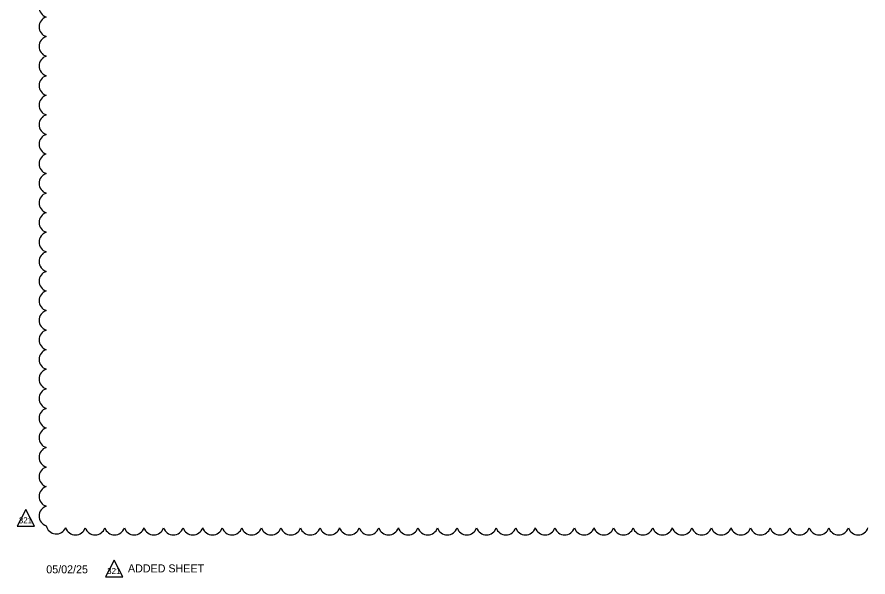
# Model space of a CAD drawing. Extents: x -811 to -795.3, y -2245.7 to -2235.4.
# Drawn here: x -811.04 to -803.6, y -2245.53 to -2240.63 of the extents above; entities that cross this region are included whole.
import ezdxf

# ---------------------------------------------------------------- set-up
doc = ezdxf.new("R2010")
doc.units = 0
doc.layers.add('ScratchEle_dp', color=7, linetype='Continuous')
doc.layers.add('TextITSLabel', color=7, linetype='Continuous')

msp = doc.modelspace()

# ---------------------------------------------------------------- linework, layer by layer
at = {"layer": 'ScratchEle_dp'}
for centre, radius, start, end in [((-810.7597, -2240.5475), 0.0897, 107.5, 252.5), ((-810.7597, -2240.7186), 0.0897, 107.5, 252.5), ((-810.7597, -2240.8897), 0.0897, 107.5, 252.5), ((-810.7597, -2241.0609), 0.0897, 107.5, 252.5), ((-810.7597, -2241.232), 0.0897, 107.5, 252.5), ((-810.7597, -2241.4031), 0.0897, 107.5, 252.5), ((-810.7597, -2241.5742), 0.0897, 107.5, 252.5), ((-810.7597, -2241.7453), 0.0897, 107.5, 252.5), ((-810.7597, -2241.9165), 0.0897, 107.5, 252.5), ((-810.7597, -2242.0876), 0.0897, 107.5, 252.5), ((-810.7597, -2242.2587), 0.0897, 107.5, 252.5), ((-810.7597, -2242.4298), 0.0897, 107.5, 252.5), ((-810.7597, -2242.601), 0.0897, 107.5, 252.5), ((-810.7597, -2242.7721), 0.0897, 107.5, 252.5), ((-810.7597, -2242.9432), 0.0897, 107.5, 252.5), ((-810.7597, -2243.1143), 0.0897, 107.5, 252.5), ((-810.7597, -2243.2854), 0.0897, 107.5, 252.5), ((-810.7597, -2243.4566), 0.0897, 107.5, 252.5), ((-810.7597, -2243.6277), 0.0897, 107.5, 252.5), ((-810.7597, -2243.7988), 0.0897, 107.5, 252.5), ((-810.7597, -2243.9699), 0.0897, 107.5, 252.5), ((-810.7597, -2244.1411), 0.0897, 107.5, 252.5), ((-810.7597, -2244.3122), 0.0897, 107.5, 252.5), ((-810.7597, -2244.4833), 0.0897, 107.5, 252.5), ((-810.7597, -2244.6544), 0.0897, 107.5, 252.5), ((-810.7597, -2244.8255), 0.0897, 107.5, 252.5), ((-810.7597, -2244.9967), 0.0897, 107.5, 252.5), ((-810.699, -2245.064), 0.0896, 191.74536, 336.74536), ((-810.531, -2245.0724), 0.0897, 197.5, 342.5), ((-810.3599, -2245.0724), 0.0897, 197.5, 342.5), ((-810.1888, -2245.0724), 0.0897, 197.5, 342.5), ((-810.0177, -2245.0724), 0.0897, 197.5, 342.5), ((-809.8466, -2245.0724), 0.0897, 197.5, 342.5), ((-809.6754, -2245.0724), 0.0897, 197.5, 342.5), ((-809.5043, -2245.0724), 0.0897, 197.5, 342.5), ((-809.3332, -2245.0724), 0.0897, 197.5, 342.5), ((-809.1621, -2245.0724), 0.0897, 197.5, 342.5), ((-808.9909, -2245.0724), 0.0897, 197.5, 342.5), ((-808.8198, -2245.0724), 0.0897, 197.5, 342.5), ((-808.6487, -2245.0724), 0.0897, 197.5, 342.5), ((-808.4776, -2245.0724), 0.0897, 197.5, 342.5), ((-808.3064, -2245.0724), 0.0897, 197.5, 342.5), ((-808.1353, -2245.0724), 0.0897, 197.5, 342.5), ((-807.9642, -2245.0724), 0.0897, 197.5, 342.5), ((-807.7931, -2245.0724), 0.0897, 197.5, 342.5), ((-807.622, -2245.0724), 0.0897, 197.5, 342.5), ((-807.4508, -2245.0724), 0.0897, 197.5, 342.5), ((-807.2797, -2245.0724), 0.0897, 197.5, 342.5), ((-807.1086, -2245.0724), 0.0897, 197.5, 342.5), ((-806.9375, -2245.0724), 0.0897, 197.5, 342.5), ((-806.7663, -2245.0724), 0.0897, 197.5, 342.5), ((-806.5952, -2245.0724), 0.0897, 197.5, 342.5), ((-806.4241, -2245.0724), 0.0897, 197.5, 342.5), ((-806.253, -2245.0724), 0.0897, 197.5, 342.5), ((-806.0819, -2245.0724), 0.0897, 197.5, 342.5), ((-805.9107, -2245.0724), 0.0897, 197.5, 342.5), ((-805.7396, -2245.0724), 0.0897, 197.5, 342.5), ((-805.5685, -2245.0724), 0.0897, 197.5, 342.5), ((-805.3974, -2245.0724), 0.0897, 197.5, 342.5), ((-805.2262, -2245.0724), 0.0897, 197.5, 342.5), ((-805.0551, -2245.0724), 0.0897, 197.5, 342.5), ((-804.884, -2245.0724), 0.0897, 197.5, 342.5), ((-804.7129, -2245.0724), 0.0897, 197.5, 342.5), ((-804.5418, -2245.0724), 0.0897, 197.5, 342.5), ((-804.3706, -2245.0724), 0.0897, 197.5, 342.5), ((-804.1995, -2245.0724), 0.0897, 197.5, 342.5), ((-804.0284, -2245.0724), 0.0897, 197.5, 342.5), ((-803.8573, -2245.0724), 0.0897, 197.5, 342.5), ((-803.6861, -2245.0724), 0.0897, 197.5, 342.5)]:
    msp.add_arc(centre, radius, start, end, dxfattribs=at)
at = {"layer": 'TextITSLabel'}
for points in [[(-810.9653, -2244.9384), (-811.0423, -2245.0868), (-810.8883, -2245.0868)], [(-810.1928, -2245.3815), (-810.2698, -2245.5298), (-810.1158, -2245.5298)]]:
    msp.add_lwpolyline(points, close=True, dxfattribs=at)

# ---------------------------------------------------------------- texts
at = {"layer": 'ScratchEle_dp'}
for s, p in [('05/02/25', (-810.7864, -2245.4978)), ('ADDED SHEET', (-810.0721, -2245.4897))]:
    msp.add_text(s, height=0.07, rotation=0, dxfattribs=at).set_placement(p)
at = {"layer": 'TextITSLabel'}
for p in [(-811.0269, -2245.0604), (-810.2544, -2245.5035)]:
    msp.add_text('321', height=0.0525, rotation=360, dxfattribs=at).set_placement(p)

doc.saveas('drawing.dxf')
